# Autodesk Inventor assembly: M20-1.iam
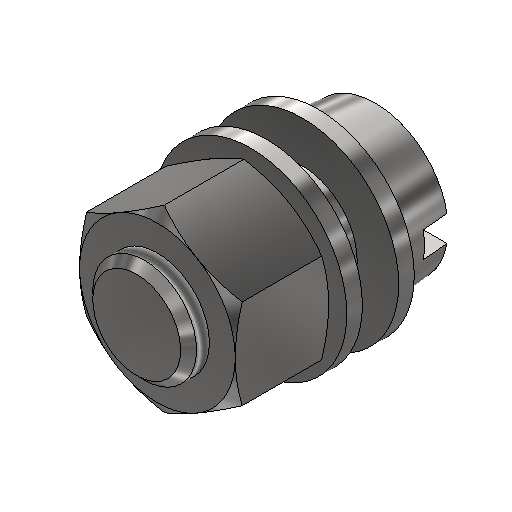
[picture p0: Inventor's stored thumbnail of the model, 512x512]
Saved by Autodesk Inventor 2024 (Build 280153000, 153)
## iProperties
Company: ATC
ClientObjectVersion: 1
Created: 2023-03
Part Number: M20-1.iam
Document SubType Name: Assembly
Designer: Andrzej Jaskulski
Checked By: A.J.
Engr Approved By: Andrzej Jaskulski
Mfg Approved By: Andrzej Jaskulski
Authority: A.J.
Author: Andrzej Jaskulski
Title: A.J.: Kurs R2024-MEP
Revision Number: 1/24
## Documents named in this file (5)
- C:\Users\AndJas\Documents\R2024-MEP\Obszar roboczy\SPEC\GOTOWE\SPEC-GOTOWE\Design Accelerator\M20-1.iam
- M20-1.iam
- C:\Users\AndJas\Documents\R2024-MEP\Obszar roboczy\SPEC\GOTOWE\SPEC-GOTOWE\PN\PN-78_M-82005 - 21.ipt
- C:\Users\AndJas\Documents\R2024-MEP\Obszar roboczy\SPEC\GOTOWE\SPEC-GOTOWE\PN\PN-85_M-82215 - M 20 x 35 - 2,5.ipt
- C:\Users\AndJas\Documents\R2024-MEP\Obszar roboczy\SPEC\GOTOWE\SPEC-GOTOWE\PN\PN-86_M-82144 - M20.ipt
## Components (4 placed, 3 different names)
1. PN-78/M-82005 21:1
2. PN-85/M-82215 M 20 x 35:1
3. PN-78/M-82005 21:2
4. PN-86/M-82144 M20:1
